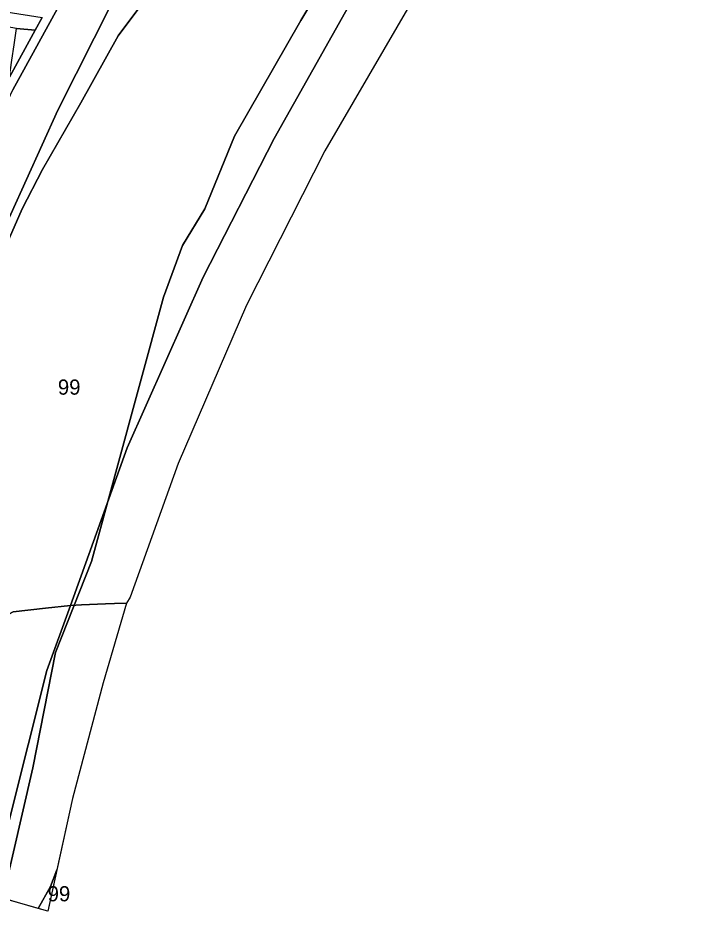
# Model space of a CAD drawing. Extents: x -537068 to -534056, y -1176840 to -1172401.
# Drawn here: x -535061.6 to -534836.4, y -1176231.2 to -1175937.1 of the extents above; entities that cross this region are included whole.
import ezdxf

# ---------------------------------------------------------------- set-up
doc = ezdxf.new("R2010")
doc.units = 0
for name, color, linetype in [('95560013', 7, 'Continuous'), ('95630013', 7, 'Continuous'), ('95640013', 7, 'Continuous'), ('95660013', 7, 'Continuous')]:
    doc.layers.add(name, color=color, linetype=linetype)

msp = doc.modelspace()

# ---------------------------------------------------------------- linework, layer by layer
at = {"layer": '95560013'}
for points in [[(-535055.84, -1175941.16), (-535062, -1175940.6), (-535102.78, -1175933.38), (-535148.13, -1175926.69), (-535148.33, -1175924.47), (-535147.9, -1175921.98), (-535101.05, -1175929.43), (-535053.54, -1175936.95)], [(-535063.51, -1175950.98), (-535062.78, -1175945.98), (-535062, -1175940.6), (-535055.84, -1175941.16), (-535064.33, -1175956.65)]]:
    msp.add_lwpolyline(points, close=True, dxfattribs=at)
at = {"layer": '95630013'}
for points in [[(-534986.37, -1176031.62), (-535008.76, -1176083.79), (-535024.61, -1176127.82), (-535025.82, -1176129.74), (-535029.79, -1176129.91), (-535032.73, -1176130.03), (-535040.62, -1176130.36), (-535044.27, -1176130.51), (-535025.61, -1176078.63), (-535000.54, -1176022.43), (-534977.24, -1175976.81), (-534951.74, -1175931.55), (-534909.46, -1175868.74), (-534853.27, -1175794.86), (-534836.42, -1175804.33), (-534844.09, -1175812.91), (-534865.58, -1175838.65), (-534900.16, -1175884.16), (-534931.82, -1175931.47), (-534960.54, -1175980.81)], [(-535151.07, -1176198.96), (-535150.89, -1176195.01), (-535151.7, -1176188.89), (-535145.91, -1176172.43), (-535138.79, -1176152.2), (-535120.43, -1176146.49), (-535115.67, -1176145.03), (-535112.79, -1176144.15), (-535106.7, -1176142.28), (-535077.57, -1176140.39), (-535063.09, -1176132.61), (-535052.46, -1176131.42), (-535044.27, -1176130.51), (-535052.03, -1176151.91), (-535070.7, -1176225.74), (-535082.15, -1176222.47), (-535130.73, -1176205.55), (-535144.25, -1176201.17)], [(-535070.7, -1176225.74), (-535052.03, -1176151.91), (-535044.27, -1176130.51), (-535040.62, -1176130.36), (-535032.73, -1176130.03), (-535029.79, -1176129.91), (-535025.82, -1176129.74), (-535033.52, -1176156.02), (-535043.53, -1176194.1), (-535051.68, -1176231.16), (-535061.71, -1176228.3)]]:
    msp.add_lwpolyline(points, close=True, dxfattribs=at)
for points in [[(-535030.38, -1175931.76), (-535048.44, -1175967.44), (-535074.28, -1176024.54), (-535097.63, -1176080.91), (-535114.32, -1176127.76), (-535118.47, -1176140.49), (-535126.55, -1176124.33), (-535127.65, -1176120.53), (-535126.42, -1176117.04), (-535123.51, -1176108.22), (-535112.98, -1176076.3), (-535089.97, -1176017.76), (-535063.2, -1175960.77), (-535033.24, -1175906.1)], [(-534951.74, -1175931.55), (-534977.24, -1175976.81), (-535000.54, -1176022.43), (-535025.61, -1176078.63), (-535044.27, -1176130.51), (-535052.46, -1176131.42), (-535063.09, -1176132.61), (-535077.57, -1176140.39), (-535106.7, -1176142.28), (-535112.79, -1176144.15), (-535115.67, -1176145.03), (-535118.47, -1176140.49), (-535114.32, -1176127.76), (-535097.63, -1176080.91), (-535074.28, -1176024.54), (-535048.44, -1175967.44), (-535030.38, -1175931.76)]]:
    msp.add_lwpolyline(points, dxfattribs=at)
at = {"layer": '95640013'}
for points in [[(-535033.24, -1175906.1), (-535063.2, -1175960.77)], [(-535064.33, -1175956.65), (-535055.84, -1175941.16), (-535053.54, -1175936.95)]]:
    msp.add_lwpolyline(points, dxfattribs=at)
at = {"layer": '95660013'}
for points in [[(-534931.82, -1175931.47), (-534960.54, -1175980.81), (-534986.37, -1176031.62), (-535008.76, -1176083.79), (-535024.61, -1176127.82), (-535025.82, -1176129.74), (-535033.52, -1176156.02), (-535043.53, -1176194.1), (-535048.69, -1176217.55), (-535050.81, -1176223), (-535054.83, -1176230.26), (-535061.71, -1176228.3), (-535066.51, -1176226.93), (-535056.62, -1176184), (-535049.12, -1176146), (-535037.37, -1176116), (-535013.62, -1176029), (-535007.37, -1176012), (-535000, -1176000), (-534990.31, -1175976), (-534968.5, -1175938), (-534943.5, -1175896)], [(-534943.5, -1175896), (-534968.5, -1175938), (-534990.31, -1175976), (-535000, -1176000), (-535007.37, -1176012), (-535013.62, -1176029), (-535037.37, -1176116), (-535049.12, -1176146), (-535056.62, -1176184), (-535066.51, -1176226.93)], [(-535018.12, -1175929), (-535028.5, -1175943), (-535040.81, -1175965), (-535053.5, -1175987), (-535060.12, -1176000), (-535065.81, -1176013)], [(-535065.81, -1176013), (-535060.12, -1176000), (-535053.5, -1175987), (-535040.81, -1175965), (-535028.5, -1175943), (-535018.12, -1175929)]]:
    msp.add_lwpolyline(points, dxfattribs=at)
msp.add_lwpolyline([(-535051.68, -1176231.16), (-535054.83, -1176230.26), (-535050.81, -1176223), (-535048.69, -1176217.55)], close=True, dxfattribs=at)

# ---------------------------------------------------------------- texts
for p in [(-535048.39, -1176061.14), (-535051.76, -1176227.93)]:
    msp.add_text('99', height=5, rotation=360, dxfattribs=at).set_placement(p)

doc.saveas('drawing.dxf')
